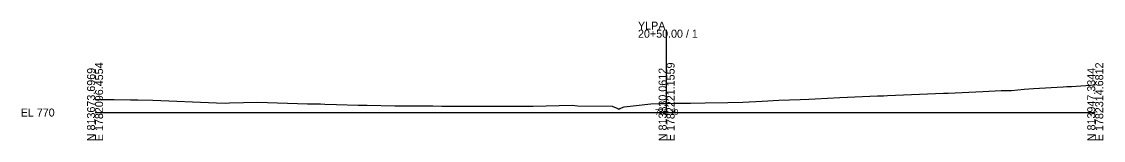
# Model space of a CAD drawing. Extents: x -76 to 1303, y -10 to 9544.
# Drawn here: x 924.3 to 1302.8, y 490.3 to 531.7 of the extents above; entities that cross this region are included whole.
import ezdxf

# ---------------------------------------------------------------- set-up
doc = ezdxf.new("R2010")
doc.units = 0
for name, color, linetype in [('Exist Cross Section Cell', 7, 'Continuous'), ('Exist XS Center Line Elevation Label', 7, 'Continuous'), ('Exist XS Ground Line', 7, 'Continuous')]:
    doc.layers.add(name, color=color, linetype=linetype)

msp = doc.modelspace()

# ---------------------------------------------------------------- linework, layer by layer
at = {"layer": 'Exist Cross Section Cell'}
for p, q in [((1150, 500), (1150, 528.93)), ((950, 500), (1150, 500)), ((1150, 500), (1300, 500))]:
    msp.add_line(p, q, dxfattribs=at)
at = {"layer": 'Exist XS Ground Line'}
for p, q in [((1248.55, 506.78), (1260.72, 507.37)), ((1260.72, 507.37), (1267.05, 507.7)), ((1267.05, 507.7), (1270.71, 507.75)), ((1270.71, 507.75), (1275.17, 508.12)), ((1275.17, 508.12), (1278.35, 508.43)), ((1278.35, 508.43), (1288.8, 509)), ((1288.8, 509), (1290.05, 509.04)), ((1290.05, 509.04), (1291.71, 509.14)), ((1291.71, 509.14), (1300, 509.64)), ((950, 504.58), (954.08, 504.51)), ((954.08, 504.51), (956.71, 504.51)), ((956.71, 504.51), (962.37, 504.47)), ((962.37, 504.47), (963.59, 504.49)), ((963.59, 504.49), (965.01, 504.49)), ((965.01, 504.49), (970.27, 504.32)), ((970.27, 504.32), (992.46, 503.37)), ((997.08, 503.38), (1006.9, 503.64)), ((1006.9, 503.64), (1024.35, 503.09)), ((1163.51, 503.38), (1171.47, 503.46)), ((1171.47, 503.46), (1176.67, 503.61)), ((1176.67, 503.61), (1183.48, 503.96)), ((1183.48, 503.96), (1189.25, 504.28)), ((1189.25, 504.28), (1196.71, 504.52)), ((1196.71, 504.52), (1199.82, 504.64)), ((1199.82, 504.64), (1202.03, 504.75)), ((1202.03, 504.75), (1210.61, 505.22)), ((1210.61, 505.22), (1223.8, 505.79)), ((1223.8, 505.79), (1225.88, 505.88)), ((1225.88, 505.88), (1227.3, 505.94)), ((1227.3, 505.94), (1246.9, 506.72)), ((1246.9, 506.72), (1247.48, 506.72)), ((1247.48, 506.72), (1248.55, 506.78)), ((992.46, 503.37), (995.8, 503.3)), ((995.8, 503.3), (997.08, 503.38)), ((1024.35, 503.09), (1028.84, 503.06)), ((1028.84, 503.06), (1030.43, 502.96)), ((1030.43, 502.96), (1034.49, 502.81)), ((1034.49, 502.81), (1042.11, 502.58)), ((1042.11, 502.58), (1045.23, 502.56)), ((1045.23, 502.56), (1054.91, 502.35)), ((1054.91, 502.35), (1068.24, 502.3)), ((1068.24, 502.3), (1071.36, 502.28)), ((1071.36, 502.28), (1076.12, 502.26)), ((1076.12, 502.26), (1097.4, 502.18)), ((1097.4, 502.18), (1103.3, 502.25)), ((1103.3, 502.25), (1116.98, 502.56)), ((1116.98, 502.56), (1118.77, 502.35)), ((1118.77, 502.35), (1131, 502.21)), ((1131, 502.21), (1132.92, 501.45)), ((1132.92, 501.45), (1133.31, 501.21)), ((1133.31, 501.21), (1133.64, 501.4)), ((1133.64, 501.4), (1135.2, 501.97)), ((1135.2, 501.97), (1139.37, 502.46)), ((1139.37, 502.46), (1144.45, 503.05)), ((1144.45, 503.05), (1147.31, 503.14)), ((1147.31, 503.14), (1150, 503.19)), ((1150, 503.19), (1152.63, 503.23)), ((1152.63, 503.23), (1158.42, 503.31)), ((1158.42, 503.31), (1163.51, 503.38))]:
    msp.add_line(p, q, dxfattribs=at)

# ---------------------------------------------------------------- texts
at = {"layer": 'Exist Cross Section Cell'}
for s, p in [('YLPA', (1140, 528.93)), ('20+50.00 / 1', (1140, 526.13)), ('EL 770', (924, 498.6))]:
    msp.add_text(s, height=2.8, dxfattribs=at).set_placement(p)
for s, p in [('N 813673.6969', (950, 490)), ('E 1782096.4554', (952.8, 490)), ('N 813830.0612', (1150, 490)), ('E 1782221.1559', (1152.8, 490)), ('N 813947.3344', (1300, 490)), ('E 1782314.6812', (1302.8, 490))]:
    msp.add_text(s, height=2.8, rotation=90, dxfattribs=at).set_placement(p)
at = {"layer": 'Exist XS Center Line Elevation Label'}
msp.add_text('773.19', height=2, dxfattribs=at).set_placement((1145.97, 499.19))

doc.saveas('drawing.dxf')
